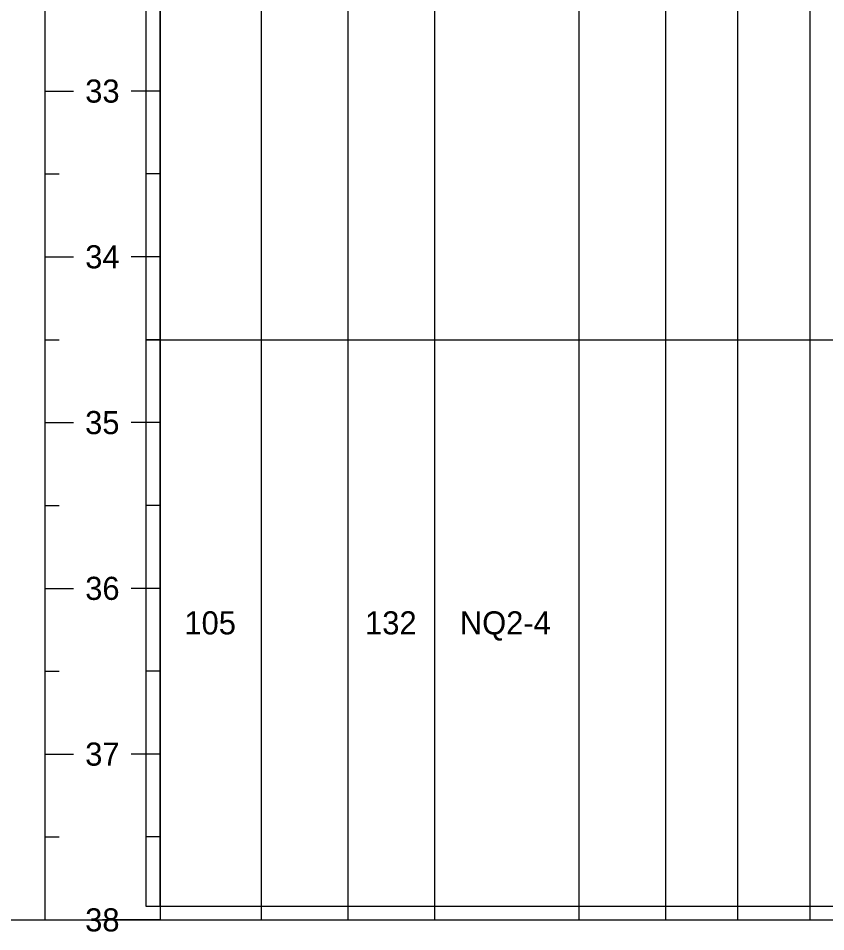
# Model space of a CAD drawing. Extents: x -0.01 to 0.83, y -0.63 to 1.27.
# Drawn here: x 0.3715 to 0.6046, y -0.6253 to -0.3617 of the extents above; entities that cross this region are included whole.
import ezdxf

# ---------------------------------------------------------------- set-up
doc = ezdxf.new("R2010")
doc.units = 0

msp = doc.modelspace()

# ---------------------------------------------------------------- linework, layer by layer
for points in [[(0.4125, 1.22083), (0.4125, -0.62183)], [(0.4125, 1.22083), (0.4125, -0.62183)], [(0.44167, 1.22083), (0.44167, -0.62183)], [(0.46667, 1.22083), (0.46667, -0.62183)], [(0.49167, 1.22083), (0.49167, -0.62183)], [(0.53333, 1.22083), (0.53333, -0.62183)], [(0.55833, 1.22083), (0.55833, -0.62183)], [(0.57917, 1.20833), (0.57917, -0.62183)], [(0.6, 1.20833), (0.6, -0.62183)], [(0.37917, 1.19583), (0.37917, -0.62183)], [(0.40833, -0.21525), (0.40833, -0.45442)], [(0.37917, -0.38267), (0.3875, -0.38267)], [(0.37917, -0.38267), (0.38333, -0.38267)], [(0.4125, -0.38267), (0.40417, -0.38267)], [(0.4125, -0.38267), (0.40833, -0.38267)], [(0.37917, -0.40658), (0.38333, -0.40658)], [(0.4125, -0.40658), (0.40833, -0.40658)], [(0.37917, -0.4305), (0.3875, -0.4305)], [(0.37917, -0.4305), (0.38333, -0.4305)], [(0.4125, -0.4305), (0.40417, -0.4305)], [(0.4125, -0.4305), (0.40833, -0.4305)], [(0.37917, -0.45442), (0.38333, -0.45442)], [(0.40833, -0.45442), (0.4125, -0.45442)], [(0.40833, -0.45442), (0.40833, -0.61785)], [(0.40833, -0.45442), (0.4125, -0.45442)], [(0.4125, -0.45442), (0.40833, -0.45442)], [(0.4125, -0.45442), (0.44167, -0.45442)], [(0.44167, -0.45442), (0.46667, -0.45442)], [(0.46667, -0.45442), (0.49167, -0.45442)], [(0.49167, -0.45442), (0.53333, -0.45442)], [(0.53333, -0.45442), (0.55833, -0.45442)], [(0.55833, -0.45442), (0.57917, -0.45442)], [(0.57917, -0.45442), (0.6, -0.45442)], [(0.6, -0.45442), (0.62083, -0.45442)], [(0.37917, -0.47833), (0.3875, -0.47833)], [(0.37917, -0.47833), (0.38333, -0.47833)], [(0.4125, -0.47833), (0.40417, -0.47833)], [(0.4125, -0.47833), (0.40833, -0.47833)], [(0.37917, -0.50225), (0.38333, -0.50225)], [(0.4125, -0.50225), (0.40833, -0.50225)], [(0.37917, -0.52617), (0.3875, -0.52617)], [(0.37917, -0.52617), (0.38333, -0.52617)], [(0.4125, -0.52617), (0.40417, -0.52617)], [(0.4125, -0.52617), (0.40833, -0.52617)], [(0.37917, -0.55008), (0.38333, -0.55008)], [(0.4125, -0.55008), (0.40833, -0.55008)], [(0.37917, -0.574), (0.3875, -0.574)], [(0.37917, -0.574), (0.38333, -0.574)], [(0.4125, -0.574), (0.40417, -0.574)], [(0.4125, -0.574), (0.40833, -0.574)], [(0.37917, -0.59792), (0.38333, -0.59792)], [(0.4125, -0.59792), (0.40833, -0.59792)], [(0.40833, -0.61785), (0.4125, -0.61785)], [(0.4125, -0.61785), (0.44167, -0.61785)], [(0.44167, -0.61785), (0.46667, -0.61785)], [(0.46667, -0.61785), (0.49167, -0.61785)], [(0.49167, -0.61785), (0.53333, -0.61785)], [(0.53333, -0.61785), (0.55833, -0.61785)], [(0.55833, -0.61785), (0.57917, -0.61785)], [(0.57917, -0.61785), (0.6, -0.61785)], [(0.6, -0.61785), (0.62083, -0.61785)], [(0.33333, -0.62183), (0.37917, -0.62183)], [(0.37917, -0.62183), (0.4125, -0.62183)], [(0.37917, -0.62183), (0.3875, -0.62183)], [(0.37917, -0.62183), (0.38333, -0.62183)], [(0.37917, -0.62183), (0.39583, -0.62183)], [(0.4125, -0.62183), (0.39583, -0.62183)], [(0.4125, -0.62183), (0.40417, -0.62183)], [(0.40833, -0.62183), (0.4125, -0.62183)], [(0.4125, -0.62183), (0.40833, -0.62183)], [(0.4125, -0.62183), (0.44167, -0.62183)], [(0.44167, -0.62183), (0.46667, -0.62183)], [(0.46667, -0.62183), (0.49167, -0.62183)], [(0.49167, -0.62183), (0.53333, -0.62183)], [(0.53333, -0.62183), (0.55833, -0.62183)], [(0.55833, -0.62183), (0.57917, -0.62183)], [(0.57917, -0.62183), (0.6, -0.62183)], [(0.6, -0.62183), (0.62083, -0.62183)]]:
    msp.add_lwpolyline(points)
for points in [[(0.40833, -0.45442), (0.4125, -0.45442), (0.4125, -0.21525), (0.40833, -0.21525)], [(0.40833, -0.61785), (0.4125, -0.61785), (0.4125, -0.45442), (0.40833, -0.45442)]]:
    msp.add_lwpolyline(points, close=True)

# ---------------------------------------------------------------- texts
for s, p in [('33', (0.39087, -0.386)), ('34', (0.39088, -0.43383)), ('35', (0.39084, -0.48167)), ('36', (0.39087, -0.5295)), ('105', (0.4195, -0.53946)), ('132', (0.47165, -0.53946)), ('NQ2-4', (0.49901, -0.53946)), ('37', (0.39087, -0.57733)), ('38', (0.39086, -0.62517))]:
    msp.add_text(s, height=0.006667).set_placement(p)

doc.saveas('drawing.dxf')
